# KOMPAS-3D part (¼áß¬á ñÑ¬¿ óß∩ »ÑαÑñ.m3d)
File: created 06.04.2016 12:01:11, last saved 22.07.2016 16:01:20.
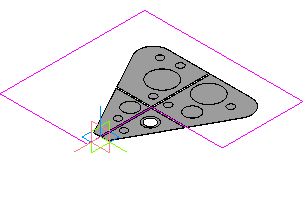
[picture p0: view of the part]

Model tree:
1. Эскиз:1
2. Операция выдавливания:1
     Толщина стенки 2 = 15; Расстояние 1 = 0.8; Расстояние 2 = 96.2519
3. Эскиз:2
4. Вырезать элемент выдавливания:1
     Толщина стенки 1 = 2; Толщина стенки 2 = 2; Расстояние 1 = 10
5. Эскиз:3
6. Вырезать элемент выдавливания:2
     Толщина стенки 1 = 2; Толщина стенки 2 = 2; Расстояние 1 = 10
7. Эскиз:4
8. Вырезать элемент выдавливания:3
     Толщина стенки 1 = 2; Толщина стенки 2 = 2; Расстояние 1 = 10
9. Эскиз:5
10. Вырезать элемент выдавливания:4
     Толщина стенки 1 = 2; Толщина стенки 2 = 2; Расстояние 1 = 0.4
11. Эскиз:6
12. Вырезать элемент выдавливания:5
     Толщина стенки 1 = 2; Толщина стенки 2 = 2; Расстояние 1 = 0.4
13. Эскиз:7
